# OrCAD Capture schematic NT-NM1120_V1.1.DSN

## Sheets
1 1) Nu-Link: size A4; title: NuLink-Me; rev: 3.0; note: 1
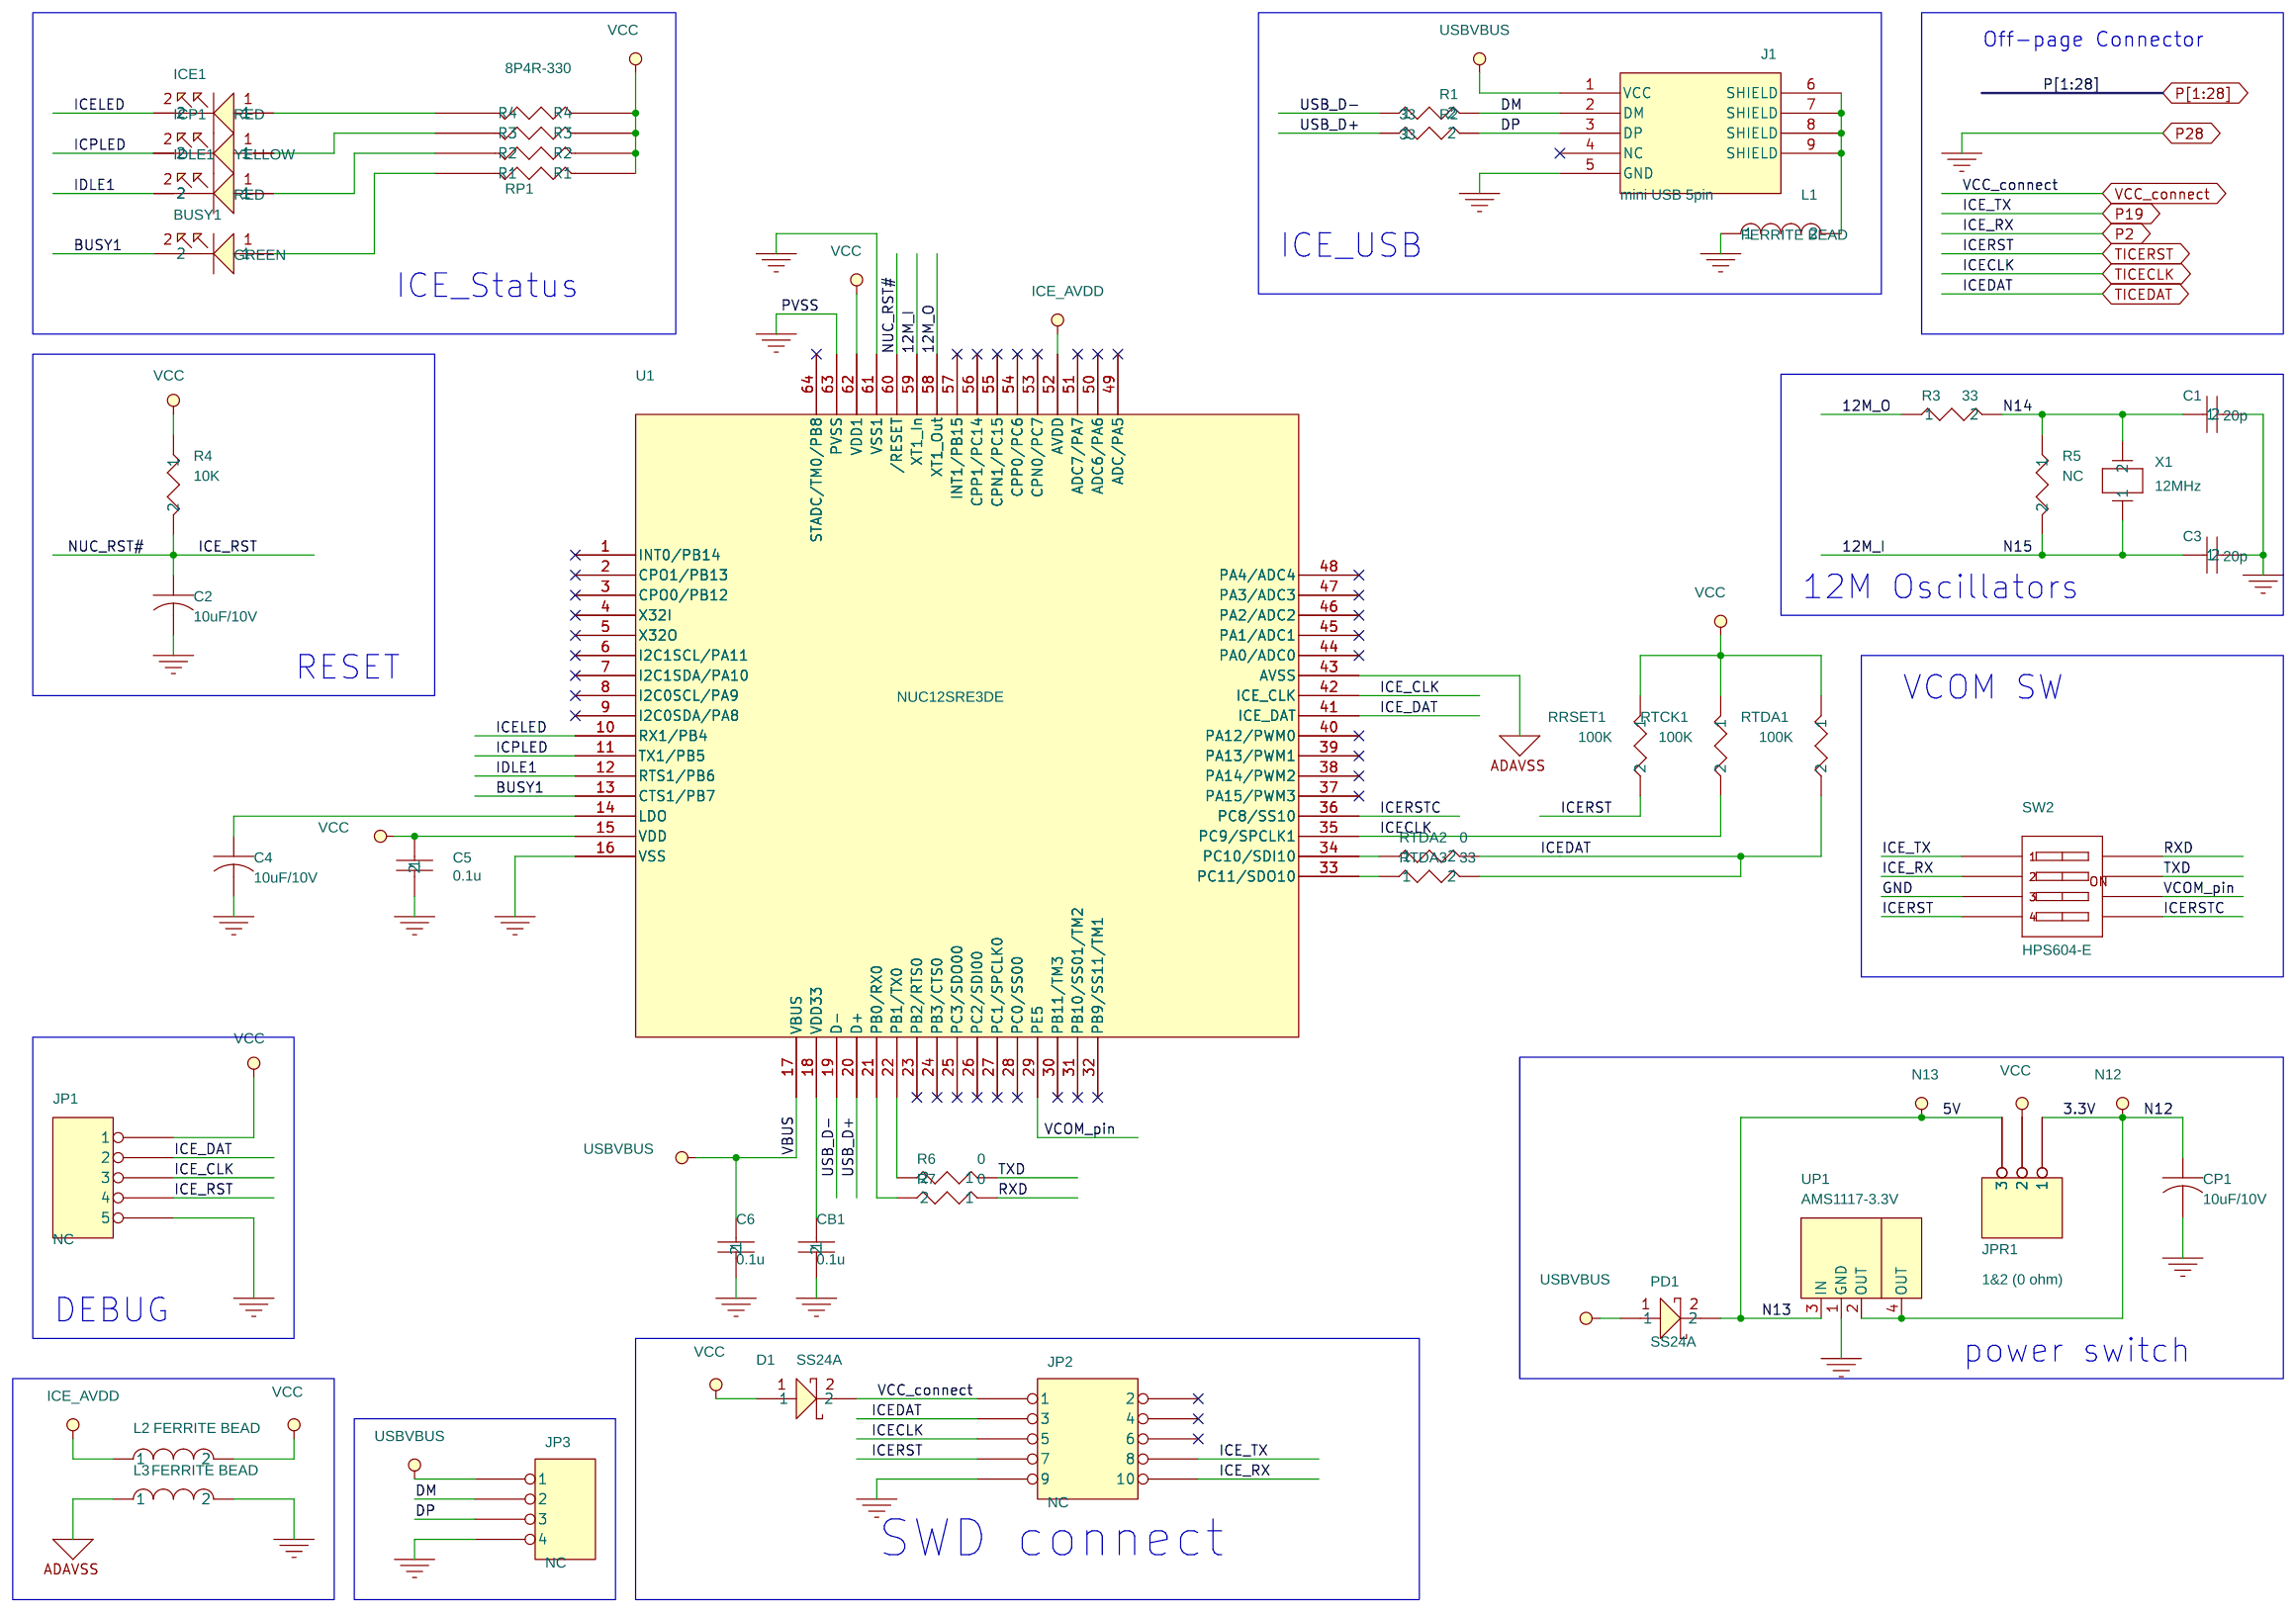
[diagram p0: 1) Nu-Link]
2 2) SDK_Circuit: size A4; title: NuTiny-SDK-NM1120; rev: 1.0
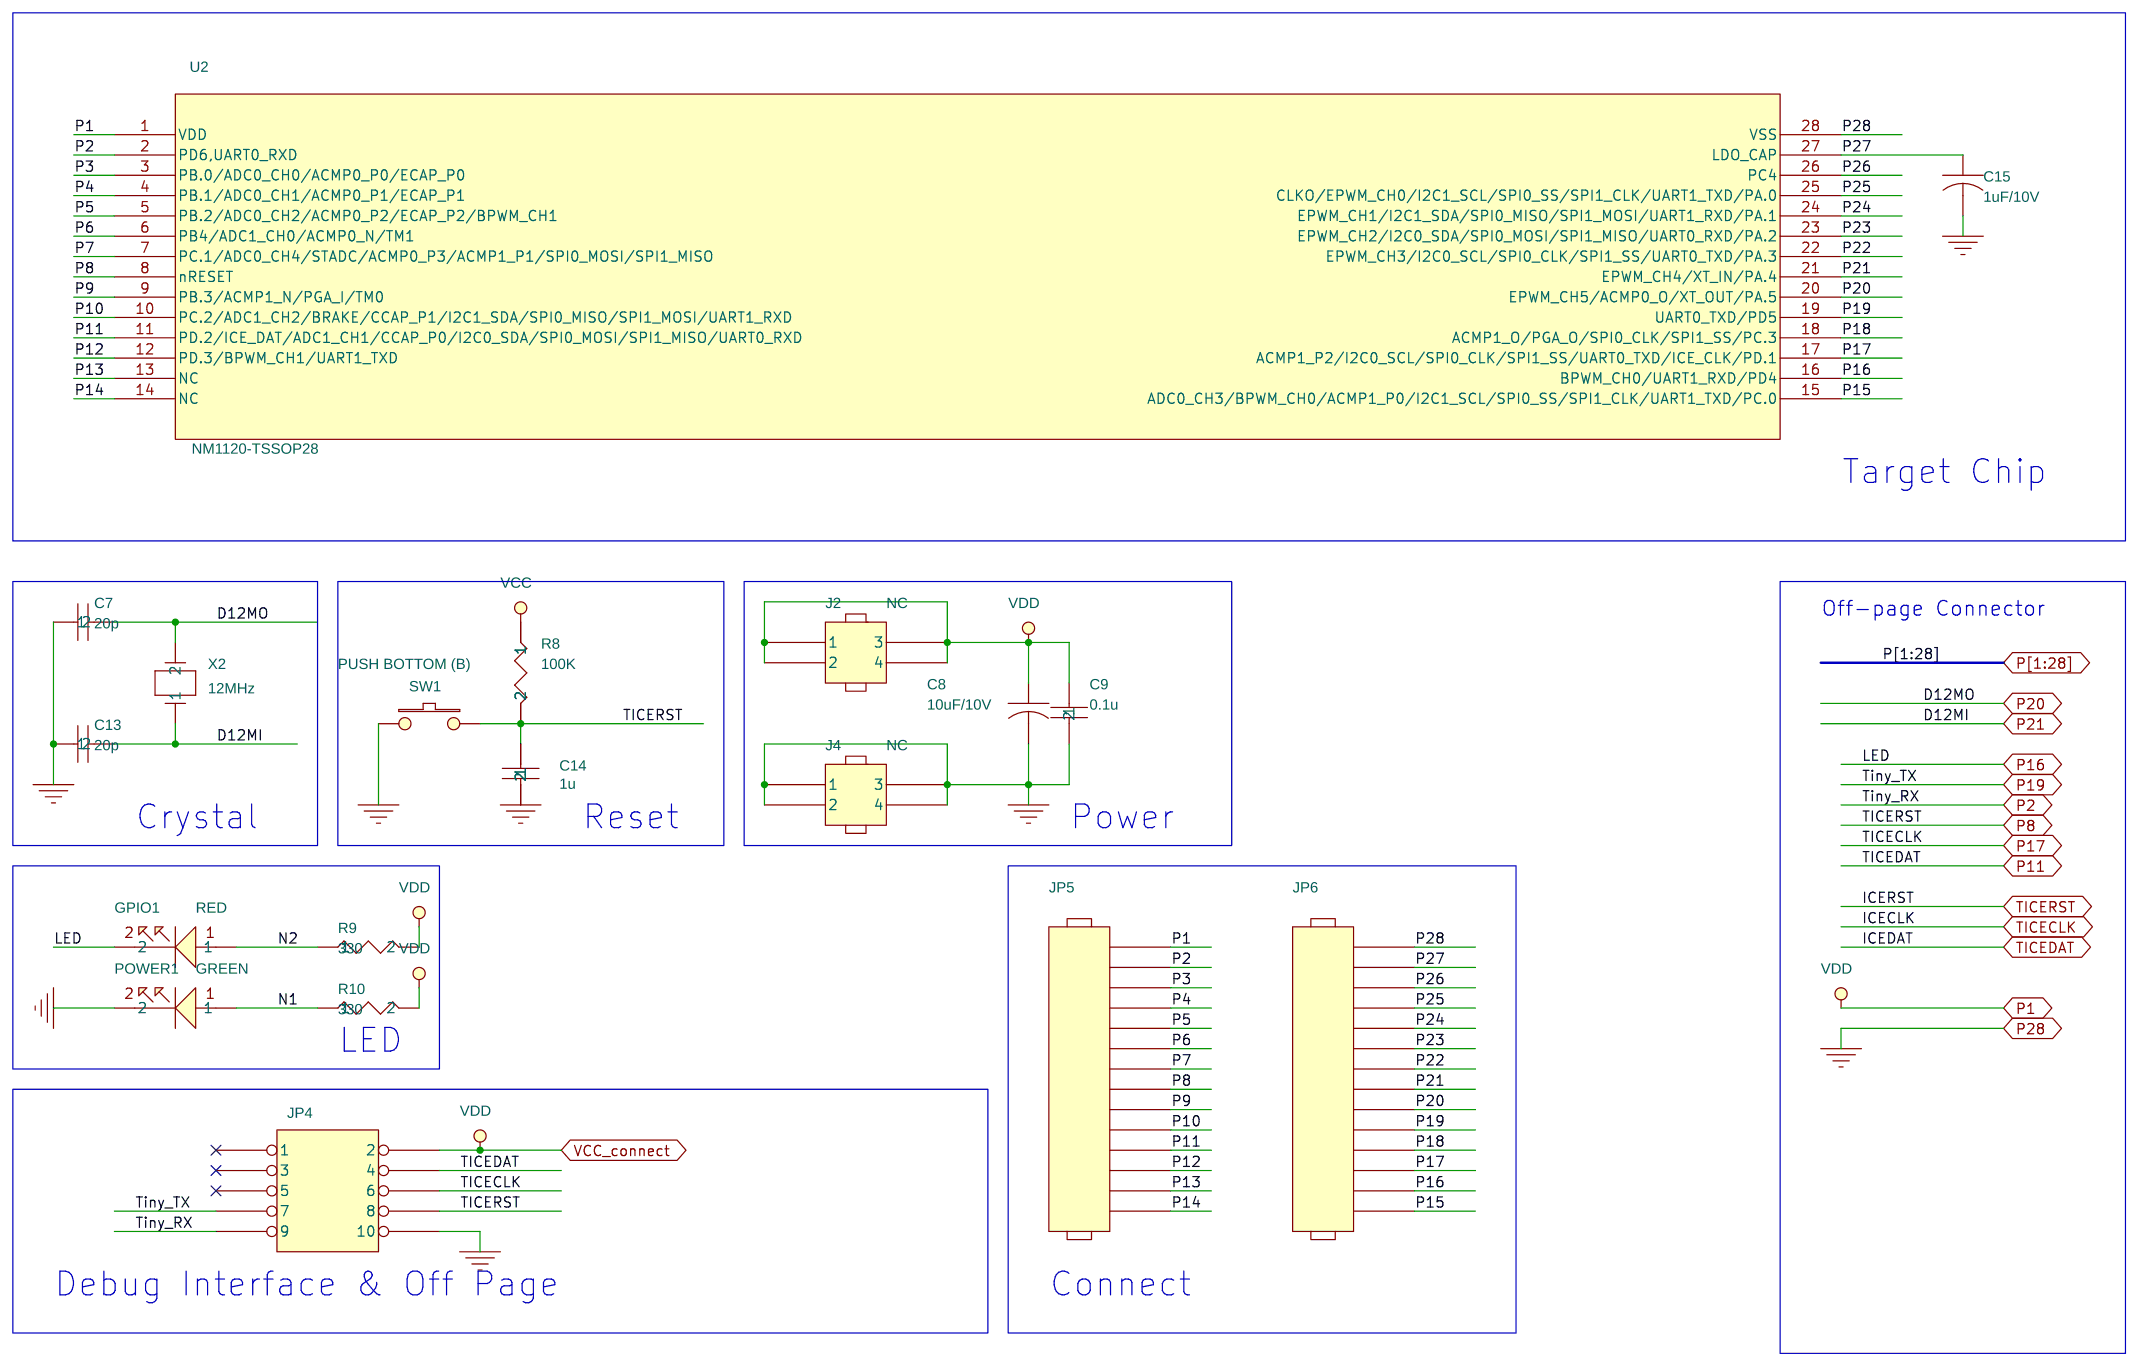
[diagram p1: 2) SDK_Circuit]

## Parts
sheet 1) Nu-Link
BUSY1  GREEN  [LED0805]
C1  20p  [C0603]
C2  10uF/10V  [TANT-A]
C3  20p  [C0603]
C4  10uF/10V  [TANT-A]
C5  0.1u  [C0603]
C6  0.1u  [C0603]
CB1  0.1u  [C0603]
CP1  10uF/10V  [TANT-A]
D1  SS24A  [RB060L]
ICE1  RED  [LED0805]
ICP1  YELLOW  [LED0805]
IDLE1  RED  [LED0805]
J1  mini USB 5pin  [MICRO_USB_AB_LS]
JP1  NC  [HEADER05]
JP2  NC  [header5x2]
JP3  NC  [HEADER04]
JPR1  1&2 (0 ohm)  [R0603X2]
L1  FERRITE BEAD  [L0603]
L2  FERRITE BEAD  [L0603]
L3  FERRITE BEAD  [L0603]
PD1  SS24A  [RB060L]
R1  33  [R0603]
R2  33  [R0603]
R3  33  [R0603]
R4  10K  [R0603]
R5  NC  [R0603]
R6  0  [R0603]
R7  0  [R0603]
RP1  8P4R-330  [8P4RA]
RRSET1  100K  [R0603]
RTCK1  100K  [R0603]
RTDA1  100K  [R0603]
RTDA2  0  [R0603]
RTDA3  33  [R0603]
SW2  HPS604-E  [SW1X4]
U1  NUC12SRE3DE  [NCU120_LQFP_64]
UP1  AMS1117-3.3V  [SOT-223-1]
X1  12MHz  [XTAL\LP\SMD]
sheet 2) SDK_Circuit
C7  20p  [C0603]
C8  10uF/10V  [TANT-A]
C9  0.1u  [C0603]
C13  20p  [C0603]
C14  1u  [C0603]
C15  1uF/10V  [TANT-A]
GPIO1  RED  [LED0805]
J2  NC  [HEADER2X2]
J4  NC  [HEADER2X2]
JP4  NC  [header5x2]
JP5  NC  [HEADER14X1]
JP6  NC  [HEADER14X1]
POWER1  GREEN  [LED0805]
R8  100K  [R0603]
R9  330  [R0603]
R10  330  [R0603]
SW1  PUSH BOTTOM (B)  [SW_SMD_HSM]
U2  NM1120-TSSOP28  [TSSOP28_1]
X2  12MHz  [XTAL\LP\SMD]

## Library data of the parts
BUSY1 POWER1 = LED_GREEN
C1 C7 = C_20p
C2 C4 C8 CP1 = C_10uF_10V
C3 C13 = C_20p_1
C5 C9 = C_0.1u
C6 = C_0.1u_1
CB1 = C_0.1u_2
D1 = D_SS24A_1
GPIO1 ICE1 = LED_RED
ICP1 = LED_YELLOW
IDLE1 = LED_RED_1
J1 = mini_USB_5pin: element_no: I0005
JP1 = HEADER_5
JP2 JP4 = HEADER_5X2
JP3 = HEADER_4
JPR1 = HEADER_3
L1 = FERRITE_BEAD_2
L2 = FERRITE_BEAD
L3 = FERRITE_BEAD_1
PD1 = D_SS24A
R1 = R_33
R2 = R_33_1
R3 = R_33_3
R4 = R_10K
R5 = R_0
R6 = R_0_3
R7 = R_0_1
RP1 = 8P4R-330
RRSET1 = R_100K_2
RTCK1 = R_100K_1
R8 RTDA1 = R_100K
RTDA2 = R_0_2
RTDA3 = R_33_2
SW2 = SW_DIP-4_2
U1 = NCU120_LQFP_1
UP1 = AMS1117-3.3V
X1 X2 = Xtal_12MHz: element_no: I0008
C14 = C_1u
C15 = C_1uF_16V
J2 J4 = HEADER_2X2
JP5 JP6 = HEADER_14
R9 = R_1K
R10 = R_1K_1
SW1 = PUSH_BOTTOM_(B)
U2 = NM1120_2

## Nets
3.3V: CP1.1 JPR1.1 UP1.2(OUT) UP1.4(OUT)
5V: JPR1.3 PD1.2 UP1.3(IN)
AVSS: L3.1 U1.43(AVSS)
VCC: C5.1 D1.1 JP1.1 JPR1.2 L2.2 R4.1 RP1.2(R1) RP1.4(R2) RP1.6(R3) RP1.8(R4) RRSET1.1 RTCK1.1 RTDA1.1 U1.15(VDD) U1.62(VDD1)
12M_I: C3.1 R5.2 U1.59(XT1_In) X1.1
12M_O: R3.1 U1.58(XT1_Out)
BUSY1: BUSY1.2 U1.13(CTS1/PB7)
DM: J1.2(DM) JP3.2 R1.2
DP: J1.3(DP) JP3.3 R2.2
ICE_AVDD: L2.1 U1.52(AVDD)
ICE_CLK: JP1.3 U1.42(ICE_CLK)
ICE_DAT: JP1.2 U1.41(ICE_DAT)
ICE_RST: C2.1 JP1.4 R4.2 U1.60(/RESET)
ICELED: ICE1.2 U1.10(RX1/PB4)
ICERSTC: SW2.5(B4) U1.36(PC8/SS10)
ICPLED: ICP1.2 U1.11(TX1/PB5)
IDLE1: IDLE1.2 U1.12(RTS1/PB6)
N1: POWER1.1 R10.1
N2: GPIO1.1 R9.1
N14: C1.1 R3.2 R5.1 X1.2
P1: C8.1 C9.1 D1.2 J2.1(3) J2.2(4) J2.3(1) J2.4(2) JP2.1 JP4.2 JP5.1 R8.1 R9.2 R10.2 U2.1(VDD)
P2: JP2.10 JP4.9 JP5.2 SW2.2(A2) U2.2(PD6,UART0_RXD)
P3: JP5.3 U2.3(PB.0/ADC0_CH0/ACMP0_P0/ECAP_P0)
P4: JP5.4 U2.4(PB.1/ADC0_CH1/ACMP0_P1/ECAP_P1)
P5: JP5.5 U2.5(PB.2/ADC0_CH2/ACMP0_P2/ECAP_P2/BPWM_CH1)
P6: JP5.6 U2.6(PB4/ADC1_CH0/ACMP0_N/TM1)
P7: JP5.7 U2.7(PC.1/ADC0_CH4/STADC/ACMP0_P3/ACMP1_P1/SPI0_MOSI/SPI1_MISO)
P8: C14.1 JP2.7 JP4.8 JP5.8 R8.2 RRSET1.2 SW1.2 SW2.4(A4) U2.8(nRESET)
P9: JP5.9 U2.9(PB.3/ACMP1_N/PGA_I/TM0)
P10: JP5.10 U2.10(PC.2/ADC1_CH2/BRAKE/CCAP_P1/I2C1_SDA/SPI0_MISO/SPI1_MOSI/UART1_RXD)
P11: JP2.3 JP4.4 JP5.11 RTDA1.2 RTDA2.2 RTDA3.2 U2.11(PD.2/ICE_DAT/ADC1_CH1/CCAP_P0/I2C0_SDA/SPI0_MOSI/SPI1_MISO/UART0_RXD)
P12: JP5.12 U2.12(PD.3/BPWM_CH1/UART1_TXD)
P13: JP5.13 U2.13(NC)
P14: JP5.14 U2.14(NC)
P15: JP6.14 U2.15(ADC0_CH3/BPWM_CH0/ACMP1_P0/I2C1_SCL/SPI0_SS/SPI1_CLK/UART1_TXD/PC.0)
P16: GPIO1.2 JP6.13 U2.16(BPWM_CH0/UART1_RXD/PD4)
P17: JP2.5 JP4.6 JP6.12 RTCK1.2 U1.35(PC9/SPCLK1) U2.17(ACMP1_P2/I2C0_SCL/SPI0_CLK/SPI1_SS/UART0_TXD/ICE_CLK/PD.1)
P18: JP6.11 U2.18(ACMP1_O/PGA_O/SPI0_CLK/SPI1_SS/PC.3)
P19: JP2.8 JP4.7 JP6.10 SW2.1(A1) U2.19(UART0_TXD/PD5)
P20: C7.2 JP6.9 U2.20(EPWM_CH5/ACMP0_O/XT_OUT/PA.5) X2.2
P21: C13.2 JP6.8 U2.21(EPWM_CH4/XT_IN/PA.4) X2.1
P22: JP6.7 U2.22(EPWM_CH3/I2C0_SCL/SPI0_CLK/SPI1_SS/UART0_TXD/PA.3)
P23: JP6.6 U2.23(EPWM_CH2/I2C0_SDA/SPI0_MOSI/SPI1_MISO/UART0_RXD/PA.2)
P24: JP6.5 U2.24(EPWM_CH1/I2C1_SDA/SPI0_MISO/SPI1_MOSI/UART1_RXD/PA.1)
P25: JP6.4 U2.25(CLKO/EPWM_CH0/I2C1_SCL/SPI0_SS/SPI1_CLK/UART1_TXD/PA.0)
P26: JP6.3 U2.26(PC4)
P27: C15.1 JP6.2 U2.27(LDO_CAP)
P28: C1.2 C2.2 C3.2 C4.2 C5.2 C6.2 C7.1 C8.2 C9.2 C13.1 C14.2 C15.2 CB1.2 CP1.2 J1.5(GND) J4.1(3) J4.2(4) J4.3(1) J4.4(2) JP1.5 JP2.9 JP3.4 JP4.10 JP6.1 L1.1 L3.2 POWER1.2 SW1.1 SW2.3(A3) U1.16(VSS) U1.61(VSS1) U1.63(PVSS) U2.28(VSS) UP1.1(GND)
RXD: R7.1 SW2.8(B1)
TXD: R6.1 SW2.7(B2)
USB_D+: R2.1 U1.20(D+)
USB_D-: R1.1 U1.19(D-)
USBVBUS: C6.1 J1.1(VCC) JP3.1 PD1.1 U1.17(VBUS)
VCOM_pin: SW2.6(B3) U1.29(PE5)
N00874: BUSY1.1 RP1.1(R1)
N00882: IDLE1.1 RP1.3(R2)
N16812063: C4.1 U1.14(LDO)
N16812255: CB1.1 U1.18(VDD33)
N16812376: RTDA3.1 U1.33(PC11/SDO10)
N17452574: R7.2 U1.21(PB0/RX0)
N17453149: R6.2 U1.22(PB1/TX0)
N17861502: RTDA2.1 U1.34(PC10/SDI10)
N18771284: J1.6(SHIELD) J1.7(SHIELD) J1.8(SHIELD) J1.9(SHIELD) L1.2
N21812882: ICE1.1 RP1.7(R4)
N21823371: ICP1.1 RP1.5(R3)

Not connected (* = marked no-connect by the designer): J1 4(NC)*; JP2 2* 4* 6*; JP4 1* 3* 5*; U1 1(INT0/PB14)* 2(CPO1/PB13)* 3(CPO0/PB12)* 4(X32I)* 5(X32O)* 6(I2C1SCL/PA11)* 7(I2C1SDA/PA10)* 8(I2C0SCL/PA9)* 9(I2C0SDA/PA8)* 23(PB2/RTS0)* 24(PB3/CTS0)* 25(PC3/SDO00)* 26(PC2/SDI00)* 27(PC1/SPCLK0)* 28(PC0/SS00)* 30(PB11/TM3)* 31(PB10/SS01/TM2)* 32(PB9/SS11/TM1)* 37(PA15/PWM3)* 38(PA14/PWM2)* 39(PA13/PWM1)* 40(PA12/PWM0)* 44(PA0/ADC0)* 45(PA1/ADC1)* 46(PA2/ADC2)* 47(PA3/ADC3)* 48(PA4/ADC4)* 49(ADC/PA5)* 50(ADC6/PA6)* 51(ADC7/PA7)* 53(CPN0/PC7)* 54(CPP0/PC6)* 55(CPN1/PC15)* 56(CPP1/PC14)* 57(INT1/PB15)* 64(STADC/TM0/PB8)*

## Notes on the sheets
sheet 1
- Off-page Connector
- ICE_USB
- ICE_Status
- 12M Oscillators
- RESET
- VCOM SW
- DEBUG
- power switch
- SWD connect
sheet 2
- Target Chip
- Off-page Connector
- Crystal
- Reset
- Power
- LED
- Debug Interface & Off Page
- Connect
